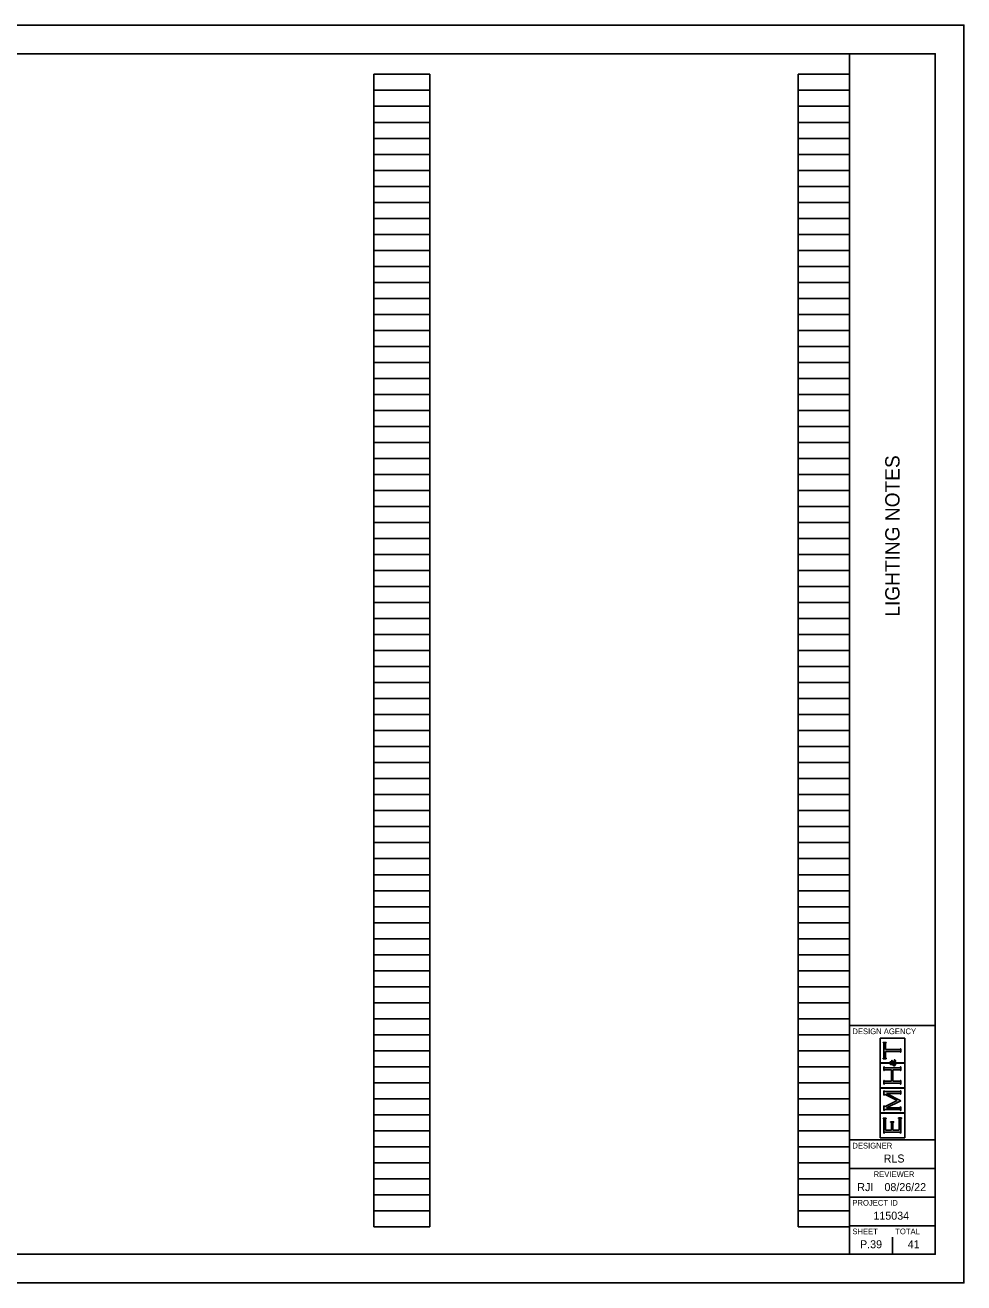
# Model space of a CAD drawing. Extents: x 0 to 34, y 0 to 22.
# Drawn here: x 17.58 to 34, y 0 to 22 of the extents above; entities that cross this region are included whole.
import ezdxf

# ---------------------------------------------------------------- set-up
doc = ezdxf.new("R2010")
doc.units = 0
for name, color, linetype in [('SH_Border', 7, 'Continuous'), ('SH_Cut_Line', 7, 'Continuous'), ('SH_Data', 7, 'Continuous')]:
    doc.layers.add(name, color=color, linetype=linetype)

msp = doc.modelspace()

# ---------------------------------------------------------------- linework, layer by layer
at = {"layer": 'SH_Border'}
for p, q in [((32, 0.5), (32, 21.5)), ((32, 4.5), (33.5, 4.5)), ((32, 2.5), (33.5, 2.5)), ((32, 2), (33.5, 2)), ((32, 1.5), (33.5, 1.5)), ((32, 1), (33.5, 1))]:
    msp.add_line(p, q, dxfattribs=at)
msp.add_lwpolyline([(1.5, 21.5), (33.5, 21.5), (33.5, 0.5), (1.5, 0.5)], close=True, dxfattribs=at)
at = {"layer": 'SH_Cut_Line'}
msp.add_lwpolyline([(0, 0), (34, 0), (34, 22), (0, 22)], close=True, dxfattribs=at)
at = {"layer": 'SH_Data'}
for p, q in [((23.68, 0.98), (23.68, 21.14)), ((23.68, 21.14), (24.66, 21.14)), ((24.66, 0.98), (24.66, 21.14)), ((31.1, 0.98), (31.1, 21.14)), ((31.1, 21.14), (32, 21.14)), ((32, 0.98), (32, 21.14)), ((23.68, 20.86), (24.66, 20.86)), ((31.1, 20.86), (32, 20.86)), ((23.68, 20.58), (24.66, 20.58)), ((31.1, 20.58), (32, 20.58)), ((23.68, 20.3), (24.66, 20.3)), ((31.1, 20.3), (32, 20.3)), ((23.68, 20.02), (24.66, 20.02)), ((31.1, 20.02), (32, 20.02)), ((23.68, 19.74), (24.66, 19.74)), ((31.1, 19.74), (32, 19.74)), ((23.68, 19.46), (24.66, 19.46)), ((31.1, 19.46), (32, 19.46)), ((23.68, 19.18), (24.66, 19.18)), ((31.1, 19.18), (32, 19.18)), ((23.68, 18.9), (24.66, 18.9)), ((31.1, 18.9), (32, 18.9)), ((23.68, 18.62), (24.66, 18.62)), ((31.1, 18.62), (32, 18.62)), ((23.68, 18.34), (24.66, 18.34)), ((31.1, 18.34), (32, 18.34)), ((23.68, 18.06), (24.66, 18.06)), ((31.1, 18.06), (32, 18.06)), ((23.68, 17.78), (24.66, 17.78)), ((31.1, 17.78), (32, 17.78)), ((23.68, 17.5), (24.66, 17.5)), ((31.1, 17.5), (32, 17.5)), ((23.68, 17.22), (24.66, 17.22)), ((31.1, 17.22), (32, 17.22)), ((23.68, 16.94), (24.66, 16.94)), ((31.1, 16.94), (32, 16.94)), ((23.68, 16.66), (24.66, 16.66)), ((31.1, 16.66), (32, 16.66)), ((23.68, 16.38), (24.66, 16.38)), ((31.1, 16.38), (32, 16.38)), ((23.68, 16.1), (24.66, 16.1)), ((31.1, 16.1), (32, 16.1)), ((23.68, 15.82), (24.66, 15.82)), ((31.1, 15.82), (32, 15.82)), ((23.68, 15.54), (24.66, 15.54)), ((31.1, 15.54), (32, 15.54)), ((23.68, 15.26), (24.66, 15.26)), ((31.1, 15.26), (32, 15.26)), ((23.68, 14.98), (24.66, 14.98)), ((31.1, 14.98), (32, 14.98)), ((23.68, 14.7), (24.66, 14.7)), ((31.1, 14.7), (32, 14.7)), ((23.68, 14.42), (24.66, 14.42)), ((31.1, 14.42), (32, 14.42)), ((23.68, 14.14), (24.66, 14.14)), ((31.1, 14.14), (32, 14.14)), ((23.68, 13.86), (24.66, 13.86)), ((31.1, 13.86), (32, 13.86)), ((23.68, 13.58), (24.66, 13.58)), ((31.1, 13.58), (32, 13.58)), ((23.68, 13.3), (24.66, 13.3)), ((31.1, 13.3), (32, 13.3)), ((23.68, 13.02), (24.66, 13.02)), ((31.1, 13.02), (32, 13.02)), ((23.68, 12.74), (24.66, 12.74)), ((31.1, 12.74), (32, 12.74)), ((23.68, 12.46), (24.66, 12.46)), ((31.1, 12.46), (32, 12.46)), ((23.68, 12.18), (24.66, 12.18)), ((31.1, 12.18), (32, 12.18)), ((23.68, 11.9), (24.66, 11.9)), ((31.1, 11.9), (32, 11.9)), ((23.68, 11.62), (24.66, 11.62)), ((31.1, 11.62), (32, 11.62)), ((23.68, 11.34), (24.66, 11.34)), ((31.1, 11.34), (32, 11.34)), ((23.68, 11.06), (24.66, 11.06)), ((31.1, 11.06), (32, 11.06)), ((23.68, 10.78), (24.66, 10.78)), ((31.1, 10.78), (32, 10.78)), ((23.68, 10.5), (24.66, 10.5)), ((31.1, 10.5), (32, 10.5)), ((23.68, 10.22), (24.66, 10.22)), ((31.1, 10.22), (32, 10.22)), ((23.68, 9.94), (24.66, 9.94)), ((31.1, 9.94), (32, 9.94)), ((23.68, 9.66), (24.66, 9.66)), ((31.1, 9.66), (32, 9.66)), ((23.68, 9.38), (24.66, 9.38)), ((31.1, 9.38), (32, 9.38)), ((23.68, 9.1), (24.66, 9.1)), ((31.1, 9.1), (32, 9.1)), ((23.68, 8.82), (24.66, 8.82)), ((31.1, 8.82), (32, 8.82)), ((23.68, 8.54), (24.66, 8.54)), ((31.1, 8.54), (32, 8.54)), ((23.68, 8.26), (24.66, 8.26)), ((31.1, 8.26), (32, 8.26)), ((23.68, 7.98), (24.66, 7.98)), ((31.1, 7.98), (32, 7.98)), ((23.68, 7.7), (24.66, 7.7)), ((31.1, 7.7), (32, 7.7)), ((23.68, 7.42), (24.66, 7.42)), ((31.1, 7.42), (32, 7.42)), ((23.68, 7.14), (24.66, 7.14)), ((31.1, 7.14), (32, 7.14)), ((23.68, 6.86), (24.66, 6.86)), ((31.1, 6.86), (32, 6.86)), ((23.68, 6.58), (24.66, 6.58)), ((31.1, 6.58), (32, 6.58)), ((23.68, 6.3), (24.66, 6.3)), ((31.1, 6.3), (32, 6.3)), ((23.68, 6.02), (24.66, 6.02)), ((31.1, 6.02), (32, 6.02)), ((23.68, 5.74), (24.66, 5.74)), ((31.1, 5.74), (32, 5.74)), ((23.68, 5.46), (24.66, 5.46)), ((31.1, 5.46), (32, 5.46)), ((23.68, 5.18), (24.66, 5.18)), ((31.1, 5.18), (32, 5.18)), ((23.68, 4.9), (24.66, 4.9)), ((31.1, 4.9), (32, 4.9)), ((23.68, 4.62), (24.66, 4.62)), ((31.1, 4.62), (32, 4.62)), ((23.68, 4.34), (24.66, 4.34)), ((31.1, 4.34), (32, 4.34)), ((32.966, 4.28), (32.534, 4.28)), ((32.534, 4.28), (32.534, 3.848)), ((32.588, 4.199), (32.588, 4.206)), ((32.588, 4.206), (32.644, 4.206)), ((32.594, 4.198), (32.588, 4.199)), ((32.598, 4.196), (32.594, 4.198)), ((32.599, 4.194), (32.598, 4.196)), ((32.601, 4.191), (32.599, 4.194)), ((32.602, 4.187), (32.601, 4.191)), ((32.602, 4.181), (32.602, 4.187)), ((32.602, 3.947), (32.602, 4.181)), ((32.632, 4.191), (32.631, 4.187)), ((32.631, 4.187), (32.631, 4.181)), ((32.631, 4.181), (32.631, 4.081)), ((32.633, 4.194), (32.632, 4.191)), ((32.635, 4.196), (32.633, 4.194)), ((32.639, 4.198), (32.635, 4.196)), ((32.644, 4.199), (32.639, 4.198)), ((32.644, 4.206), (32.644, 4.199)), ((32.966, 3.848), (32.966, 4.28)), ((23.68, 4.06), (24.66, 4.06)), ((31.1, 4.06), (32, 4.06)), ((32.631, 4.081), (32.872, 4.081)), ((32.872, 4.047), (32.631, 4.047)), ((32.631, 4.047), (32.631, 3.947)), ((32.872, 4.081), (32.878, 4.081)), ((32.878, 4.047), (32.872, 4.047)), ((32.878, 4.081), (32.882, 4.082)), ((32.883, 4.046), (32.878, 4.047)), ((32.882, 4.082), (32.885, 4.084)), ((32.885, 4.044), (32.883, 4.046)), ((32.885, 4.084), (32.887, 4.085)), ((32.888, 4.042), (32.885, 4.044)), ((32.887, 4.085), (32.889, 4.089)), ((32.889, 4.039), (32.888, 4.042)), ((32.889, 4.089), (32.891, 4.095)), ((32.891, 4.033), (32.889, 4.039)), ((32.891, 4.095), (32.898, 4.095)), ((32.898, 4.033), (32.891, 4.033)), ((32.898, 4.095), (32.898, 4.033)), ((23.68, 3.78), (24.66, 3.78)), ((31.1, 3.78), (32, 3.78)), ((32.534, 3.848), (32.693, 3.848)), ((32.693, 3.842), (32.534, 3.842)), ((32.534, 3.842), (32.534, 3.41)), ((32.588, 3.928), (32.594, 3.93)), ((32.588, 3.921), (32.588, 3.928)), ((32.644, 3.921), (32.588, 3.921)), ((32.594, 3.93), (32.598, 3.932)), ((32.598, 3.932), (32.599, 3.934)), ((32.599, 3.934), (32.601, 3.937)), ((32.601, 3.937), (32.602, 3.941)), ((32.602, 3.941), (32.602, 3.947)), ((32.602, 3.714), (32.602, 3.776)), ((32.602, 3.776), (32.609, 3.776)), ((32.609, 3.776), (32.611, 3.77)), ((32.611, 3.77), (32.612, 3.766)), ((32.612, 3.766), (32.615, 3.765)), ((32.615, 3.765), (32.617, 3.763)), ((32.617, 3.763), (32.622, 3.762)), ((32.622, 3.762), (32.628, 3.762)), ((32.628, 3.762), (32.872, 3.762)), ((32.631, 3.947), (32.631, 3.941)), ((32.631, 3.941), (32.632, 3.937)), ((32.632, 3.937), (32.633, 3.934)), ((32.633, 3.934), (32.635, 3.932)), ((32.635, 3.932), (32.639, 3.93)), ((32.639, 3.93), (32.644, 3.928)), ((32.644, 3.928), (32.644, 3.921)), ((32.693, 3.848), (32.693, 3.842)), ((32.701, 3.852), (32.703, 3.857)), ((32.701, 3.846), (32.701, 3.852)), ((32.701, 3.84), (32.701, 3.846)), ((32.703, 3.835), (32.701, 3.84)), ((32.703, 3.857), (32.706, 3.861)), ((32.706, 3.83), (32.703, 3.835)), ((32.706, 3.861), (32.71, 3.864)), ((32.707, 3.852), (32.706, 3.849)), ((32.706, 3.849), (32.706, 3.846)), ((32.706, 3.846), (32.706, 3.842)), ((32.706, 3.842), (32.708, 3.839)), ((32.71, 3.824), (32.706, 3.83)), ((32.71, 3.854), (32.707, 3.852)), ((32.708, 3.839), (32.711, 3.837)), ((32.71, 3.864), (32.714, 3.866)), ((32.712, 3.856), (32.71, 3.854)), ((32.717, 3.821), (32.71, 3.824)), ((32.711, 3.837), (32.714, 3.835)), ((32.715, 3.857), (32.712, 3.856)), ((32.714, 3.866), (32.719, 3.866)), ((32.714, 3.835), (32.716, 3.834)), ((32.718, 3.857), (32.715, 3.857)), ((32.716, 3.834), (32.719, 3.834)), ((32.725, 3.821), (32.717, 3.821)), ((32.723, 3.857), (32.718, 3.857)), ((32.719, 3.866), (32.724, 3.866)), ((32.719, 3.834), (32.722, 3.834)), ((32.722, 3.834), (32.724, 3.834)), ((32.727, 3.856), (32.723, 3.857)), ((32.724, 3.866), (32.728, 3.864)), ((32.724, 3.834), (32.727, 3.835)), ((32.728, 3.821), (32.725, 3.821)), ((32.73, 3.853), (32.727, 3.856)), ((32.727, 3.835), (32.73, 3.836)), ((32.728, 3.864), (32.732, 3.861)), ((32.731, 3.822), (32.728, 3.821)), ((32.734, 3.85), (32.73, 3.853)), ((32.73, 3.836), (32.734, 3.837)), ((32.734, 3.822), (32.731, 3.822)), ((32.732, 3.861), (32.736, 3.857)), ((32.737, 3.845), (32.734, 3.85)), ((32.734, 3.837), (32.74, 3.839)), ((32.737, 3.823), (32.734, 3.822)), ((32.736, 3.857), (32.74, 3.851)), ((32.74, 3.839), (32.737, 3.845)), ((32.741, 3.825), (32.737, 3.823)), ((32.738, 3.867), (32.738, 3.898)), ((32.738, 3.898), (32.741, 3.898)), ((32.741, 3.867), (32.738, 3.867)), ((32.74, 3.851), (32.745, 3.842)), ((32.741, 3.898), (32.741, 3.894)), ((32.741, 3.894), (32.742, 3.891)), ((32.742, 3.871), (32.741, 3.869)), ((32.741, 3.869), (32.741, 3.867)), ((32.746, 3.827), (32.741, 3.825)), ((32.742, 3.891), (32.744, 3.889)), ((32.743, 3.872), (32.742, 3.871)), ((32.745, 3.873), (32.743, 3.872)), ((32.744, 3.889), (32.745, 3.887)), ((32.745, 3.887), (32.75, 3.883)), ((32.747, 3.874), (32.745, 3.873)), ((32.745, 3.842), (32.755, 3.848)), ((32.753, 3.815), (32.746, 3.827)), ((32.749, 3.874), (32.747, 3.874)), ((32.756, 3.874), (32.749, 3.874)), ((32.75, 3.883), (32.757, 3.879)), ((32.757, 3.832), (32.751, 3.829)), ((32.751, 3.829), (32.755, 3.824)), ((32.759, 3.808), (32.753, 3.815)), ((32.755, 3.848), (32.765, 3.855)), ((32.755, 3.824), (32.758, 3.819)), ((32.764, 3.87), (32.756, 3.874)), ((32.757, 3.879), (32.765, 3.875)), ((32.762, 3.835), (32.757, 3.832)), ((32.758, 3.819), (32.762, 3.817)), ((32.765, 3.803), (32.759, 3.808)), ((32.766, 3.838), (32.762, 3.835)), ((32.762, 3.817), (32.766, 3.814)), ((32.775, 3.861), (32.764, 3.87)), ((32.765, 3.875), (32.772, 3.87)), ((32.765, 3.855), (32.775, 3.861)), ((32.77, 3.799), (32.765, 3.803)), ((32.77, 3.84), (32.766, 3.838)), ((32.766, 3.814), (32.771, 3.812)), ((32.776, 3.845), (32.77, 3.84)), ((32.776, 3.797), (32.77, 3.799)), ((32.771, 3.812), (32.775, 3.812)), ((32.772, 3.87), (32.779, 3.865)), ((32.775, 3.812), (32.78, 3.812)), ((32.785, 3.851), (32.776, 3.845)), ((32.782, 3.797), (32.776, 3.797)), ((32.779, 3.865), (32.784, 3.869)), ((32.78, 3.812), (32.785, 3.814)), ((32.781, 3.9), (32.783, 3.902)), ((32.785, 3.899), (32.781, 3.9)), ((32.788, 3.797), (32.782, 3.797)), ((32.783, 3.902), (32.79, 3.901)), ((32.784, 3.869), (32.787, 3.873)), ((32.788, 3.897), (32.785, 3.899)), ((32.789, 3.846), (32.785, 3.851)), ((32.785, 3.814), (32.789, 3.817)), ((32.787, 3.873), (32.789, 3.876)), ((32.789, 3.895), (32.788, 3.897)), ((32.793, 3.8), (32.788, 3.797)), ((32.791, 3.892), (32.789, 3.895)), ((32.789, 3.876), (32.791, 3.88)), ((32.794, 3.859), (32.789, 3.855)), ((32.789, 3.855), (32.795, 3.849)), ((32.792, 3.842), (32.789, 3.846)), ((32.789, 3.817), (32.793, 3.821)), ((32.79, 3.901), (32.795, 3.898)), ((32.792, 3.89), (32.791, 3.892)), ((32.791, 3.88), (32.792, 3.883)), ((32.792, 3.886), (32.792, 3.89)), ((32.792, 3.883), (32.792, 3.886)), ((32.793, 3.839), (32.792, 3.842)), ((32.794, 3.837), (32.793, 3.839)), ((32.793, 3.821), (32.795, 3.825)), ((32.797, 3.804), (32.793, 3.8)), ((32.798, 3.864), (32.794, 3.859)), ((32.795, 3.834), (32.794, 3.837)), ((32.795, 3.898), (32.799, 3.894)), ((32.795, 3.849), (32.798, 3.843)), ((32.795, 3.831), (32.795, 3.834)), ((32.795, 3.825), (32.795, 3.831)), ((32.801, 3.809), (32.797, 3.804)), ((32.8, 3.868), (32.798, 3.864)), ((32.798, 3.843), (32.8, 3.839)), ((32.799, 3.894), (32.802, 3.89)), ((32.802, 3.872), (32.8, 3.868)), ((32.8, 3.839), (32.802, 3.834)), ((32.803, 3.815), (32.801, 3.809)), ((32.802, 3.89), (32.803, 3.885)), ((32.803, 3.876), (32.802, 3.872)), ((32.802, 3.834), (32.803, 3.829)), ((32.803, 3.885), (32.803, 3.88)), ((32.803, 3.88), (32.803, 3.876)), ((32.807, 3.842), (32.803, 3.848)), ((32.803, 3.848), (32.966, 3.848)), ((32.803, 3.829), (32.803, 3.823)), ((32.803, 3.823), (32.803, 3.815)), ((32.966, 3.842), (32.807, 3.842)), ((32.872, 3.762), (32.878, 3.762)), ((32.878, 3.762), (32.882, 3.763)), ((32.882, 3.763), (32.885, 3.765)), ((32.885, 3.765), (32.887, 3.766)), ((32.887, 3.766), (32.889, 3.77)), ((32.889, 3.77), (32.891, 3.776)), ((32.891, 3.776), (32.898, 3.776)), ((32.898, 3.776), (32.898, 3.714)), ((32.966, 3.41), (32.966, 3.842)), ((32.609, 3.714), (32.602, 3.714)), ((32.602, 3.477), (32.602, 3.538)), ((32.602, 3.538), (32.609, 3.538)), ((32.61, 3.72), (32.609, 3.714)), ((32.609, 3.538), (32.611, 3.533)), ((32.612, 3.723), (32.61, 3.72)), ((32.611, 3.533), (32.612, 3.529)), ((32.615, 3.725), (32.612, 3.723)), ((32.612, 3.529), (32.615, 3.527)), ((32.617, 3.727), (32.615, 3.725)), ((32.615, 3.527), (32.617, 3.526)), ((32.622, 3.728), (32.617, 3.727)), ((32.617, 3.526), (32.622, 3.525)), ((32.628, 3.728), (32.622, 3.728)), ((32.622, 3.525), (32.628, 3.525)), ((32.732, 3.728), (32.628, 3.728)), ((32.628, 3.525), (32.732, 3.525)), ((32.732, 3.525), (32.732, 3.728)), ((32.872, 3.728), (32.76, 3.728)), ((32.76, 3.728), (32.76, 3.525)), ((32.76, 3.525), (32.872, 3.525)), ((32.878, 3.728), (32.872, 3.728)), ((32.872, 3.525), (32.878, 3.525)), ((32.883, 3.727), (32.878, 3.728)), ((32.878, 3.525), (32.883, 3.525)), ((32.885, 3.725), (32.883, 3.727)), ((32.883, 3.525), (32.885, 3.527)), ((32.888, 3.723), (32.885, 3.725)), ((32.885, 3.527), (32.888, 3.529)), ((32.889, 3.72), (32.888, 3.723)), ((32.888, 3.529), (32.889, 3.533)), ((32.891, 3.714), (32.889, 3.72)), ((32.889, 3.533), (32.891, 3.538)), ((32.898, 3.714), (32.891, 3.714)), ((32.891, 3.538), (32.898, 3.538)), ((32.898, 3.538), (32.898, 3.477)), ((23.68, 3.5), (24.66, 3.5)), ((31.1, 3.5), (32, 3.5)), ((32.534, 3.41), (32.966, 3.41)), ((32.966, 3.405), (32.534, 3.405)), ((32.534, 3.405), (32.534, 2.973)), ((32.609, 3.477), (32.602, 3.477)), ((32.602, 3.283), (32.602, 3.36)), ((32.602, 3.36), (32.609, 3.36)), ((32.61, 3.482), (32.609, 3.477)), ((32.609, 3.36), (32.611, 3.354)), ((32.612, 3.486), (32.61, 3.482)), ((32.611, 3.354), (32.612, 3.351)), ((32.615, 3.488), (32.612, 3.486)), ((32.612, 3.351), (32.615, 3.349)), ((32.617, 3.49), (32.615, 3.488)), ((32.615, 3.349), (32.617, 3.347)), ((32.622, 3.491), (32.617, 3.49)), ((32.617, 3.347), (32.622, 3.346)), ((32.628, 3.491), (32.622, 3.491)), ((32.622, 3.346), (32.628, 3.346)), ((32.872, 3.491), (32.628, 3.491)), ((32.628, 3.346), (32.872, 3.346)), ((32.872, 3.312), (32.649, 3.312)), ((32.649, 3.312), (32.898, 3.186)), ((32.75, 3.5), (32.75, 3.5)), ((32.878, 3.491), (32.872, 3.491)), ((32.872, 3.346), (32.878, 3.346)), ((32.878, 3.312), (32.872, 3.312)), ((32.883, 3.49), (32.878, 3.491)), ((32.878, 3.346), (32.882, 3.347)), ((32.883, 3.311), (32.878, 3.312)), ((32.882, 3.347), (32.885, 3.349)), ((32.885, 3.488), (32.883, 3.49)), ((32.885, 3.31), (32.883, 3.311)), ((32.887, 3.486), (32.885, 3.488)), ((32.885, 3.349), (32.887, 3.351)), ((32.887, 3.308), (32.885, 3.31)), ((32.887, 3.351), (32.889, 3.354)), ((32.889, 3.304), (32.887, 3.308)), ((32.889, 3.482), (32.887, 3.486)), ((32.891, 3.477), (32.889, 3.482)), ((32.889, 3.354), (32.891, 3.36)), ((32.891, 3.298), (32.889, 3.304)), ((32.898, 3.477), (32.891, 3.477)), ((32.891, 3.36), (32.898, 3.36)), ((32.898, 3.36), (32.898, 3.298)), ((32.966, 2.973), (32.966, 3.405)), ((23.68, 3.22), (24.66, 3.22)), ((31.1, 3.22), (32, 3.22)), ((32.609, 3.283), (32.602, 3.283)), ((32.602, 3.017), (32.602, 3.094)), ((32.602, 3.094), (32.609, 3.094)), ((32.612, 3.29), (32.609, 3.283)), ((32.609, 3.094), (32.612, 3.087)), ((32.615, 3.293), (32.612, 3.29)), ((32.612, 3.087), (32.615, 3.083)), ((32.618, 3.293), (32.615, 3.293)), ((32.615, 3.083), (32.618, 3.083)), ((32.621, 3.293), (32.618, 3.293)), ((32.618, 3.083), (32.62, 3.083)), ((32.62, 3.083), (32.625, 3.086)), ((32.626, 3.292), (32.621, 3.293)), ((32.625, 3.086), (32.635, 3.09)), ((32.633, 3.288), (32.626, 3.292)), ((32.831, 3.189), (32.633, 3.288)), ((32.635, 3.09), (32.831, 3.189)), ((32.898, 3.186), (32.649, 3.062)), ((32.898, 3.298), (32.891, 3.298)), ((23.68, 2.94), (24.66, 2.94)), ((31.1, 2.94), (32, 2.94)), ((32.534, 2.973), (32.966, 2.973)), ((32.966, 2.967), (32.534, 2.967)), ((32.534, 2.967), (32.534, 2.535)), ((32.588, 2.874), (32.588, 2.881)), ((32.588, 2.881), (32.644, 2.881)), ((32.594, 2.873), (32.588, 2.874)), ((32.598, 2.871), (32.594, 2.873)), ((32.599, 2.868), (32.598, 2.871)), ((32.601, 2.866), (32.599, 2.868)), ((32.602, 2.862), (32.601, 2.866)), ((32.609, 3.017), (32.602, 3.017)), ((32.602, 2.856), (32.602, 2.862)), ((32.61, 3.023), (32.609, 3.017)), ((32.612, 3.026), (32.61, 3.023)), ((32.615, 3.028), (32.612, 3.026)), ((32.617, 3.03), (32.615, 3.028)), ((32.622, 3.031), (32.617, 3.03)), ((32.628, 3.031), (32.622, 3.031)), ((32.872, 3.031), (32.628, 3.031)), ((32.632, 2.866), (32.631, 2.862)), ((32.631, 2.862), (32.631, 2.856)), ((32.633, 2.868), (32.632, 2.866)), ((32.635, 2.871), (32.633, 2.868)), ((32.639, 2.873), (32.635, 2.871)), ((32.644, 2.874), (32.639, 2.873)), ((32.644, 2.881), (32.644, 2.874)), ((32.649, 3.062), (32.872, 3.062)), ((32.855, 2.877), (32.855, 2.884)), ((32.855, 2.884), (32.912, 2.884)), ((32.861, 2.876), (32.855, 2.877)), ((32.865, 2.874), (32.861, 2.876)), ((32.867, 2.872), (32.865, 2.874)), ((32.868, 2.869), (32.867, 2.872)), ((32.869, 2.865), (32.868, 2.869)), ((32.869, 2.859), (32.869, 2.865)), ((32.872, 3.062), (32.878, 3.062)), ((32.878, 3.031), (32.872, 3.031)), ((32.878, 3.062), (32.882, 3.063)), ((32.883, 3.03), (32.878, 3.031)), ((32.882, 3.063), (32.885, 3.065)), ((32.885, 3.028), (32.883, 3.03)), ((32.885, 3.065), (32.887, 3.067)), ((32.887, 3.026), (32.885, 3.028)), ((32.887, 3.067), (32.889, 3.07)), ((32.889, 3.023), (32.887, 3.026)), ((32.889, 3.07), (32.891, 3.076)), ((32.891, 3.017), (32.889, 3.023)), ((32.891, 3.076), (32.898, 3.076)), ((32.898, 3.017), (32.891, 3.017)), ((32.898, 3.076), (32.898, 3.017)), ((32.899, 2.869), (32.898, 2.865)), ((32.898, 2.865), (32.898, 2.858)), ((32.901, 2.871), (32.899, 2.869)), ((32.903, 2.874), (32.901, 2.871)), ((32.906, 2.876), (32.903, 2.874)), ((32.912, 2.877), (32.906, 2.876)), ((32.912, 2.884), (32.912, 2.877)), ((32.966, 2.535), (32.966, 2.967)), ((23.68, 2.66), (24.66, 2.66)), ((31.1, 2.66), (32, 2.66)), ((32.602, 2.621), (32.602, 2.856)), ((32.631, 2.856), (32.631, 2.669)), ((32.631, 2.669), (32.732, 2.669)), ((32.718, 2.81), (32.718, 2.816)), ((32.718, 2.816), (32.774, 2.816)), ((32.723, 2.808), (32.718, 2.81)), ((32.727, 2.806), (32.723, 2.808)), ((32.729, 2.804), (32.727, 2.806)), ((32.731, 2.801), (32.729, 2.804)), ((32.732, 2.797), (32.731, 2.801)), ((32.732, 2.791), (32.732, 2.797)), ((32.732, 2.669), (32.732, 2.791)), ((32.761, 2.801), (32.76, 2.797)), ((32.76, 2.797), (32.76, 2.791)), ((32.76, 2.791), (32.76, 2.669)), ((32.76, 2.669), (32.869, 2.669)), ((32.763, 2.804), (32.761, 2.801)), ((32.765, 2.806), (32.763, 2.804)), ((32.768, 2.808), (32.765, 2.806)), ((32.774, 2.81), (32.768, 2.808)), ((32.774, 2.816), (32.774, 2.81)), ((32.869, 2.669), (32.869, 2.859)), ((32.898, 2.858), (32.898, 2.621)), ((32.534, 2.535), (32.966, 2.535)), ((32.609, 2.621), (32.602, 2.621)), ((32.611, 2.626), (32.609, 2.621)), ((32.612, 2.63), (32.611, 2.626)), ((32.615, 2.632), (32.612, 2.63)), ((32.617, 2.634), (32.615, 2.632)), ((32.622, 2.635), (32.617, 2.634)), ((32.628, 2.635), (32.622, 2.635)), ((32.872, 2.635), (32.628, 2.635)), ((32.878, 2.635), (32.872, 2.635)), ((32.883, 2.634), (32.878, 2.635)), ((32.885, 2.632), (32.883, 2.634)), ((32.887, 2.63), (32.885, 2.632)), ((32.889, 2.627), (32.887, 2.63)), ((32.891, 2.621), (32.889, 2.627)), ((32.898, 2.621), (32.891, 2.621)), ((23.68, 2.38), (24.66, 2.38)), ((31.1, 2.38), (32, 2.38)), ((23.68, 2.1), (24.66, 2.1)), ((31.1, 2.1), (32, 2.1)), ((23.68, 1.82), (24.66, 1.82)), ((31.1, 1.82), (32, 1.82)), ((23.68, 1.54), (24.66, 1.54)), ((31.1, 1.54), (32, 1.54)), ((23.68, 1.26), (24.66, 1.26)), ((31.1, 1.26), (32, 1.26)), ((23.68, 0.98), (24.66, 0.98)), ((31.1, 0.98), (32, 0.98)), ((32.375, 0.675), (32.375, 0.675)), ((32.75, 0.5), (32.75, 0.8))]:
    msp.add_line(p, q, dxfattribs=at)

# ---------------------------------------------------------------- texts
msp.add_text('LIGHTING NOTES', height=0.25, rotation=90, dxfattribs=at).set_placement((32.875, 11.653))
for s, height, p in [('DESIGN AGENCY', 0.1, (32.05, 4.35)), ('DESIGNER', 0.1, (32.05, 2.35)), ('RLS', 0.14, (32.597, 2.105)), ('REVIEWER', 0.1, (32.422, 1.85)), ('RJI', 0.14, (32.136, 1.605)), ('08/26/22', 0.14, (32.611, 1.605)), ('PROJECT ID', 0.1, (32.05, 1.35)), ('115034', 0.14, (32.418, 1.105)), ('SHEET', 0.1, (32.05, 0.85)), ('TOTAL', 0.1, (32.8, 0.85)), ('P.39', 0.14, (32.184, 0.605)), ('41', 0.14, (33.019, 0.605))]:
    msp.add_text(s, height=height, dxfattribs=at).set_placement(p)

doc.saveas('drawing.dxf')
